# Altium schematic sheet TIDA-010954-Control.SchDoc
size 431 x 279 mm; Date: Not shown in title block; ApprovedBy: Not shown in title block; CheckedBy: Not shown in title block; Author: Not shown in title block; CompanyName: Not shown in title block; Engineer: Not shown in title block; Organization: Not shown in title block; Address1: Not shown in title block; Address2: Not shown in title block; Address3: Not shown in title block; Address4: Not shown in title block; DocumentNumber: 2; Revision: Use project parameter SCH_Rev; SheetNumber: 8; SheetTotal: 9; PageSetup: Record=PageOptions¦CenterHorizontal=True¦CenterVertical=True¦PrintScale=1.00¦XCorrection=1.00¦YCorrection=1.00¦PrintKind=0¦BorderSize=5000000¦LeftOffset=0¦BottomOffset=0¦Orientation=2¦PaperLength=1000¦PaperWidth=1000¦Scale=100¦PaperSource=15¦PrintQuality=600¦MediaType=1¦DitherType=10¦PaperKind=Letter¦PrintScaleMode=1
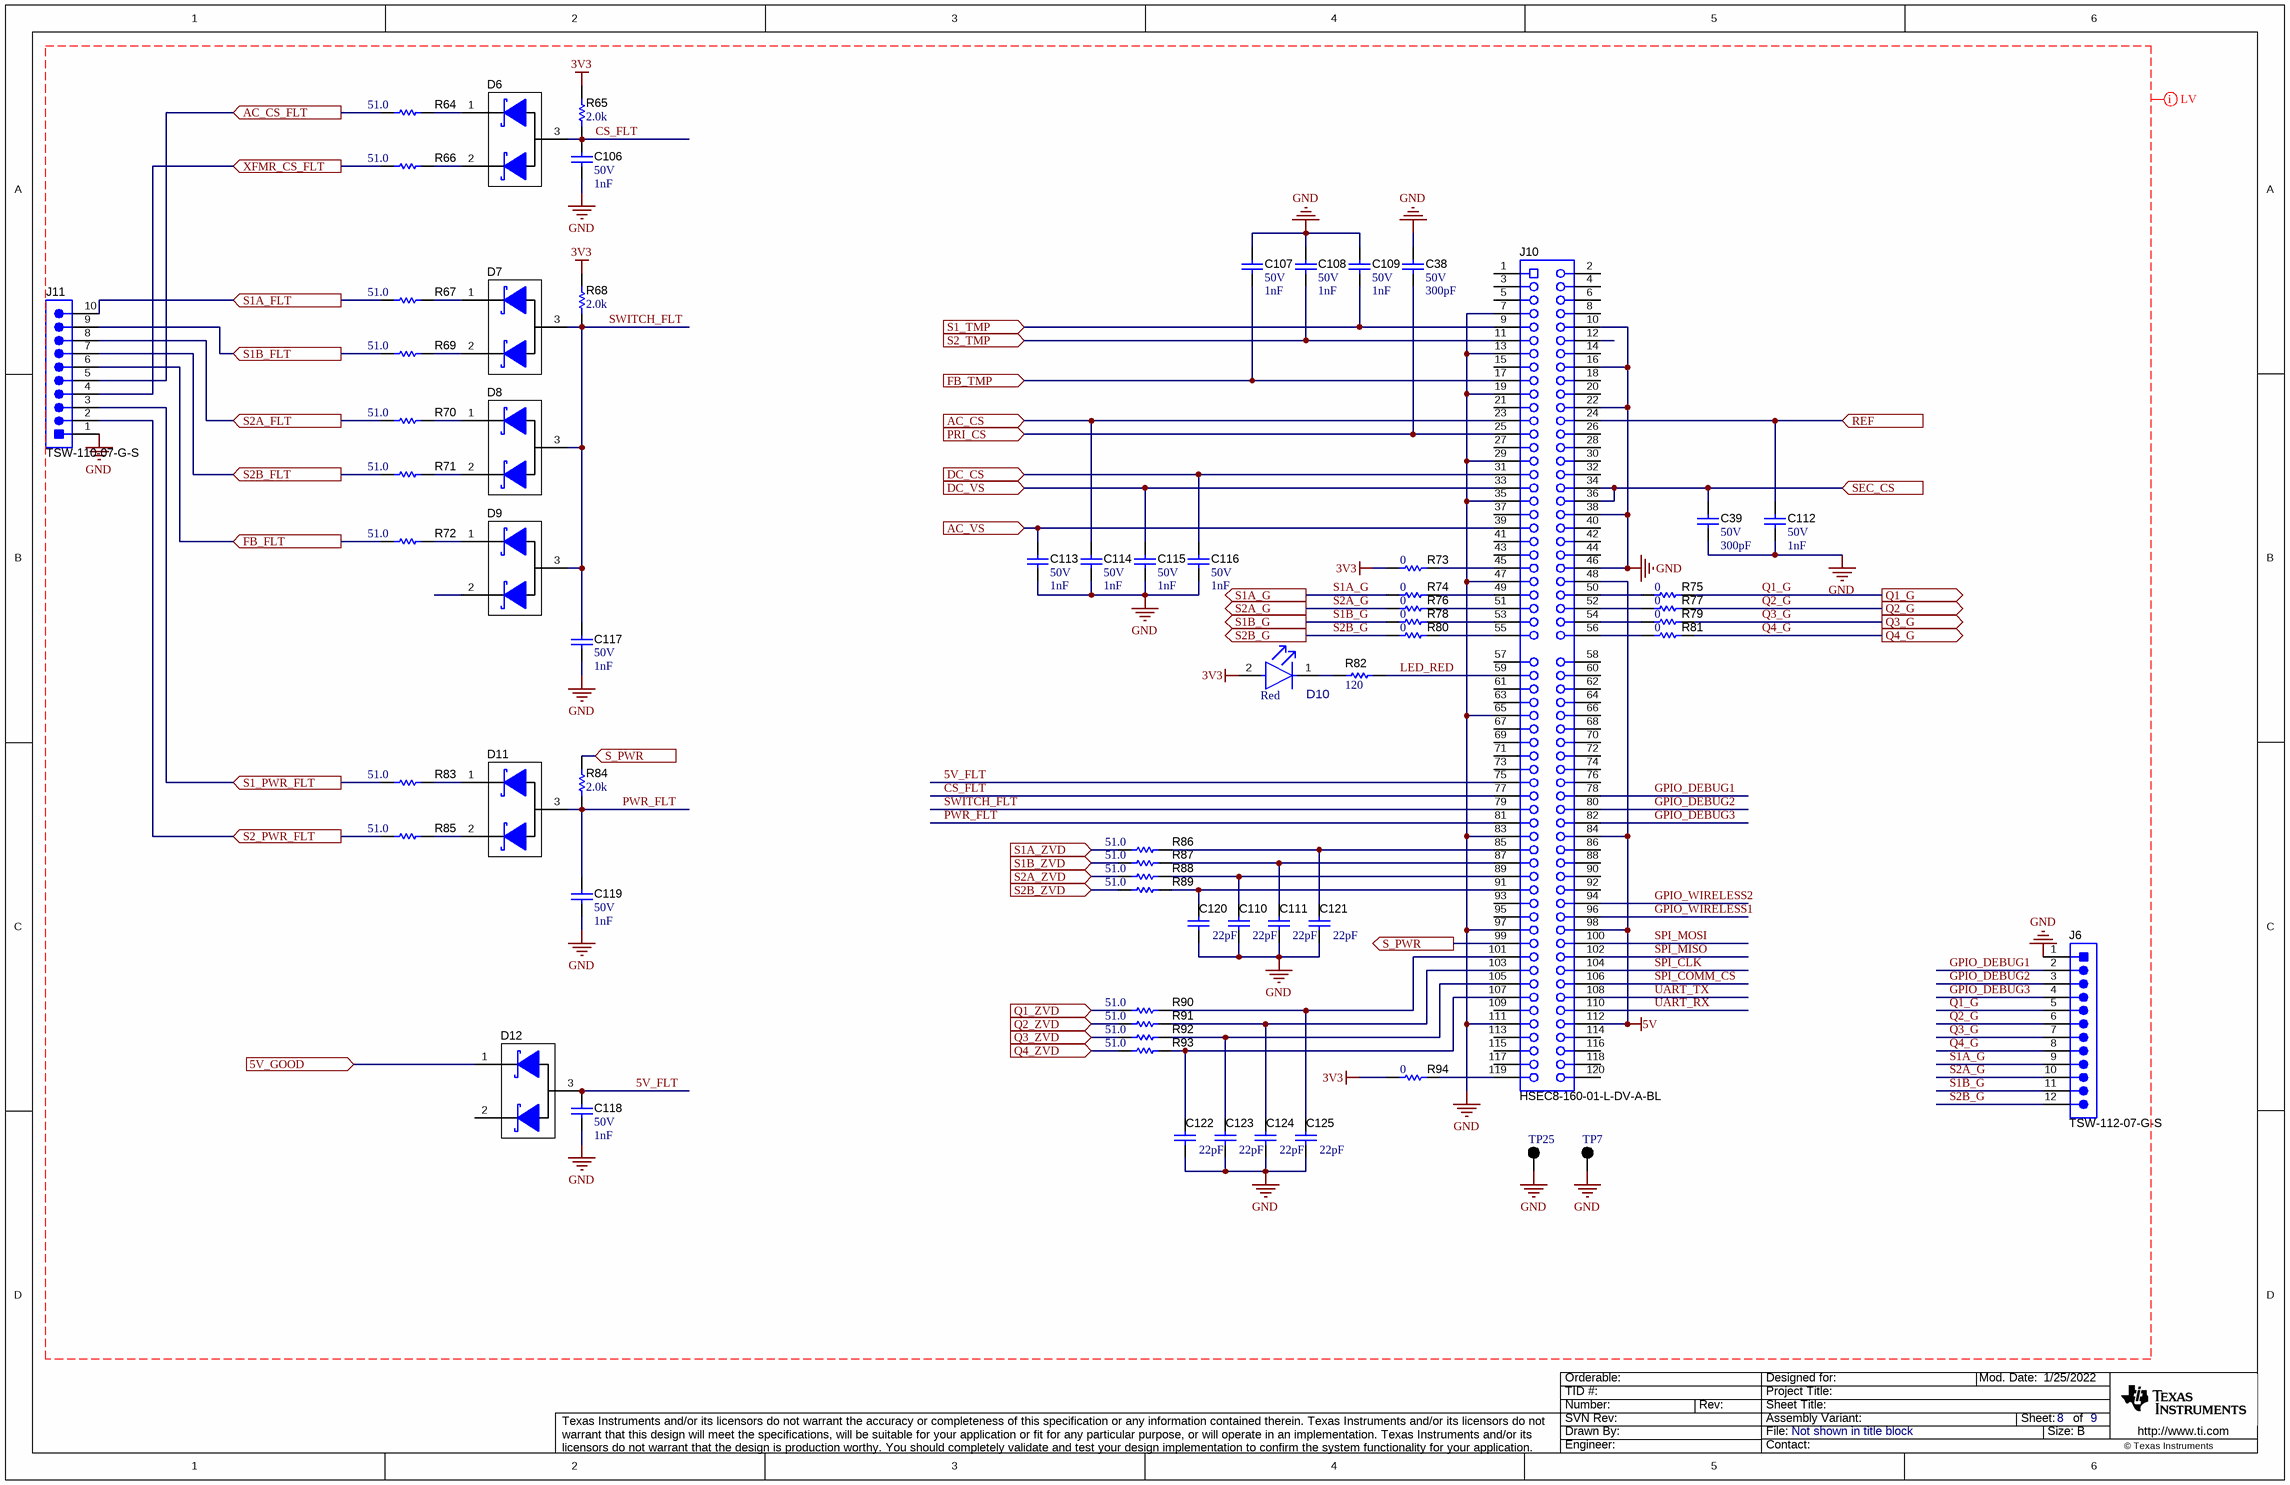
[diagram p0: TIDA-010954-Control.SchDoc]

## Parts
C38  VDC_V: 50V  ValueDisplayed: 300pF  [0603]  (hidden comment: GRM1885C1H301JA01D)
C39  VDC_V: 50V  ValueDisplayed: 300pF  [0603]  (hidden comment: GRM1885C1H301JA01D)
C106  VDC_V: 50V  ValueDisplayed: 1nF  [0603]  (hidden comment: GRM1885C1H102JA01D)
C107  VDC_V: 50V  ValueDisplayed: 1nF  [0603]  (hidden comment: GRM1885C1H102JA01D)
C108  VDC_V: 50V  ValueDisplayed: 1nF  [0603]  (hidden comment: GRM1885C1H102JA01D)
C109  VDC_V: 50V  ValueDisplayed: 1nF  [0603]  (hidden comment: GRM1885C1H102JA01D)
C110  ValueDisplayed: 22pF  [0603]  (hidden comment: GRM1885C1H220JA01D)
C111  ValueDisplayed: 22pF  [0603]  (hidden comment: GRM1885C1H220JA01D)
C112  VDC_V: 50V  ValueDisplayed: 1nF  [0603]  (hidden comment: GRM1885C1H102JA01D)
C113  VDC_V: 50V  ValueDisplayed: 1nF  [0603]  (hidden comment: GRM1885C1H102JA01D)
C114  VDC_V: 50V  ValueDisplayed: 1nF  [0603]  (hidden comment: GRM1885C1H102JA01D)
C115  VDC_V: 50V  ValueDisplayed: 1nF  [0603]  (hidden comment: GRM1885C1H102JA01D)
C116  VDC_V: 50V  ValueDisplayed: 1nF  [0603]  (hidden comment: GRM1885C1H102JA01D)
C117  VDC_V: 50V  ValueDisplayed: 1nF  [0603]  (hidden comment: GRM1885C1H102JA01D)
C118  VDC_V: 50V  ValueDisplayed: 1nF  [0603]  (hidden comment: GRM1885C1H102JA01D)
C119  VDC_V: 50V  ValueDisplayed: 1nF  [0603]  (hidden comment: GRM1885C1H102JA01D)
C120  ValueDisplayed: 22pF  [0603]  (hidden comment: GRM1885C1H220JA01D)
C121  ValueDisplayed: 22pF  [0603]  (hidden comment: GRM1885C1H220JA01D)
C122  ValueDisplayed: 22pF  [0603]  (hidden comment: GRM1885C1H220JA01D)
C123  ValueDisplayed: 22pF  [0603]  (hidden comment: GRM1885C1H220JA01D)
C124  ValueDisplayed: 22pF  [0603]  (hidden comment: GRM1885C1H220JA01D)
C125  ValueDisplayed: 22pF  [0603]  (hidden comment: GRM1885C1H220JA01D)
D6  BAT54AWT-TP  [SOT-323]  (value not drawn)
D7  BAT54AWT-TP  [SOT-323]  (value not drawn)
D8  BAT54AWT-TP  [SOT-323]  (value not drawn)
D9  BAT54AWT-TP  [SOT-323]  (value not drawn)
D10  Color: Red  [FP-APG1608SURKC_T_0603-MFG]  (hidden comment: APG1608SURKC/T)
D11  BAT54AWT-TP  [SOT-323]  (value not drawn)
D12  BAT54AWT-TP  [SOT-323]  (value not drawn)
J6  TSW-112-07-G-S  [TSW-112-07-G-S]
J10  HSEC8-160-01-L-DV-A-BL  [controlCARD-120HSEC]
J11  TSW-110-07-G-S  [TSW-110-07-G-S]
R64  ValueDisplayed: 51.0  [0603]  (hidden comment: RC0603FR-0751RL)
R65  ValueDisplayed: 2.0k  [0603]  (hidden comment: RC0603JR-072KL)
R66  ValueDisplayed: 51.0  [0603]  (hidden comment: RC0603FR-0751RL)
R67  ValueDisplayed: 51.0  [0603]  (hidden comment: RC0603FR-0751RL)
R68  ValueDisplayed: 2.0k  [0603]  (hidden comment: RC0603JR-072KL)
R69  ValueDisplayed: 51.0  [0603]  (hidden comment: RC0603FR-0751RL)
R70  ValueDisplayed: 51.0  [0603]  (hidden comment: RC0603FR-0751RL)
R71  ValueDisplayed: 51.0  [0603]  (hidden comment: RC0603FR-0751RL)
R72  ValueDisplayed: 51.0  [0603]  (hidden comment: RC0603FR-0751RL)
R73  ValueDisplayed: 0  [0603]  (hidden comment: RC0603JR-070RL)
R74  ValueDisplayed: 0  [0603]  (hidden comment: RC0603JR-070RL)
R75  ValueDisplayed: 0  [0603]  (hidden comment: RC0603JR-070RL)
R76  ValueDisplayed: 0  [0603]  (hidden comment: RC0603JR-070RL)
R77  ValueDisplayed: 0  [0603]  (hidden comment: RC0603JR-070RL)
R78  ValueDisplayed: 0  [0603]  (hidden comment: RC0603JR-070RL)
R79  ValueDisplayed: 0  [0603]  (hidden comment: RC0603JR-070RL)
R80  ValueDisplayed: 0  [0603]  (hidden comment: RC0603JR-070RL)
R81  ValueDisplayed: 0  [0603]  (hidden comment: RC0603JR-070RL)
R82  ValueDisplayed: 120  [0603]  (hidden comment: RC0603FR-07120RL)
R83  ValueDisplayed: 51.0  [0603]  (hidden comment: RC0603FR-0751RL)
R84  ValueDisplayed: 2.0k  [0603]  (hidden comment: RC0603JR-072KL)
R85  ValueDisplayed: 51.0  [0603]  (hidden comment: RC0603FR-0751RL)
R86  ValueDisplayed: 51.0  [0603]  (hidden comment: RC0603FR-0751RL)
R87  ValueDisplayed: 51.0  [0603]  (hidden comment: RC0603FR-0751RL)
R88  ValueDisplayed: 51.0  [0603]  (hidden comment: RC0603FR-0751RL)
R89  ValueDisplayed: 51.0  [0603]  (hidden comment: RC0603FR-0751RL)
R90  ValueDisplayed: 51.0  [0603]  (hidden comment: RC0603FR-0751RL)
R91  ValueDisplayed: 51.0  [0603]  (hidden comment: RC0603FR-0751RL)
R92  ValueDisplayed: 51.0  [0603]  (hidden comment: RC0603FR-0751RL)
R93  ValueDisplayed: 51.0  [0603]  (hidden comment: RC0603FR-0751RL)
R94  ValueDisplayed: 0  [0603]  (hidden comment: RC0603JR-070RL)
TP7  5011  [Keystone5011]  (value not drawn)
TP25  5011  [Keystone5011]  (value not drawn)

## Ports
5V_GOOD (in), AC_CS (in), AC_CS_FLT (in), AC_VS (in), DC_CS (in), DC_VS (in), FB_FLT (in), FB_TMP (in), PRI_CS (in), Q1_G (out), Q1_ZVD (in), Q2_G (out), Q2_ZVD (in), Q3_G (out), Q3_ZVD (in), Q4_G (out), Q4_ZVD (in), REF (in), S1_PWR_FLT (in), S1_TMP (in), S1A_FLT (in), S1A_G (out), S1A_ZVD (in), S1B_FLT (in), S1B_G (out), S1B_ZVD (in), S2_PWR_FLT (in), S2_TMP (in), S2A_FLT (in), S2A_G (out), S2A_ZVD (in), S2B_FLT (in), S2B_G (out), S2B_ZVD (in), S_PWR (in), S_PWR (out), SEC_CS (in), XFMR_CS_FLT (in)

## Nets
3V3: D10.2(ANODE) R65.2 R68.2 R73.1 R94.1
5V: J10.48 J10.84 J10.98 J10.112
GND: C38.2 C39.2 C106.2 C107.1 C108.1 C109.1 C110.2 C111.2 C112.2 C113.2 C114.2 C115.2 C116.2 C117.2 C118.2 C119.2 C120.2 C121.2 C122.2 C123.2 C124.2 C125.2 J6.1 J10.7 J10.10 J10.13 J10.16 J10.19 J10.22 J10.29 J10.35 J10.38 J10.46 J10.47 J10.65 J10.83 J10.97 J10.111 J11.1 TP7.1 TP25.1
5V_FLT: C118.1 D12.3(A) J10.75
5V_GOOD: D12.1(A) ; port 5V_GOOD
AC_CS: C114.1 J10.23 ; port AC_CS
AC_CS_FLT: J11.5 R64.1 ; port AC_CS_FLT
AC_VS: C113.1 J10.39 ; port AC_VS
CS_FLT: C106.1 D6.3(A) J10.77 R65.1
DC_CS: C116.1 J10.31 ; port DC_CS
DC_VS: C115.1 J10.33 ; port DC_VS
FB_FLT: J11.6 R72.1 ; port FB_FLT
FB_TMP: C107.2 J10.17 ; port FB_TMP
GPIO_DEBUG1: J6.2 J10.78
GPIO_DEBUG2: J6.3 J10.80
GPIO_DEBUG3: J6.4 J10.82
GPIO_WIRELESS1: J10.96
GPIO_WIRELESS2: J10.94
LED_RED: J10.59 R82.2
PRI_CS: C38.1 J10.25 ; port PRI_CS
PWR_FLT: C119.1 D11.3(A) J10.81 R84.1
Q1_G: J6.5 R75.2 ; port Q1_G
Q1_ZVD: R90.1 ; port Q1_ZVD
Q2_G: J6.6 R77.2 ; port Q2_G
Q2_ZVD: R91.1 ; port Q2_ZVD
Q3_G: J6.7 R79.2 ; port Q3_G
Q3_ZVD: R92.1 ; port Q3_ZVD
Q4_G: J6.8 R81.2 ; port Q4_G
Q4_ZVD: R93.1 ; port Q4_ZVD
REF: C112.1 J10.24 ; port REF
S1_PWR_FLT: J11.3 R83.1 ; port S1_PWR_FLT
S1_TMP: C109.2 J10.9 ; port S1_TMP
S1A_FLT: J11.10 R67.1 ; port S1A_FLT
S1A_G: J6.9 R74.1 ; port S1A_G
S1A_ZVD: R86.1 ; port S1A_ZVD
S1B_FLT: J11.9 R69.1 ; port S1B_FLT
S1B_G: J6.11 R78.1 ; port S1B_G
S1B_ZVD: R87.1 ; port S1B_ZVD
S2_PWR_FLT: J11.2 R85.1 ; port S2_PWR_FLT
S2_TMP: C108.2 J10.11 ; port S2_TMP
S2A_FLT: J11.8 R70.1 ; port S2A_FLT
S2A_G: J6.10 R76.1 ; port S2A_G
S2A_ZVD: R88.1 ; port S2A_ZVD
S2B_FLT: J11.7 R71.1 ; port S2B_FLT
S2B_G: J6.12 R80.1 ; port S2B_G
S2B_ZVD: R89.1 ; port S2B_ZVD
S_PWR: J10.99 R84.2 ; port S_PWR
SEC_CS: C39.1 J10.34 J10.36 ; port SEC_CS
SPI_CLK: J10.104
SPI_COMM_CS: J10.106
SPI_MISO: J10.102
SPI_MOSI: J10.100
SWITCH_FLT: C117.1 D7.3(A) D8.3(A) D9.3(A) J10.79 R68.1
UART_RX: J10.110
UART_TX: J10.108
XFMR_CS_FLT: J11.4 R66.1 ; port XFMR_CS_FLT
NetC110_1: C110.1 J10.89 R88.2
NetC111_1: C111.1 J10.87 R87.2
NetC120_1: C120.1 J10.91 R89.2
NetC121_1: C121.1 J10.85 R86.2
NetC122_1: C122.1 J10.107 R93.2
NetC123_1: C123.1 J10.105 R92.2
NetC124_1: C124.1 J10.103 R91.2
NetC125_1: C125.1 J10.101 R90.2
NetD6_1: D6.1(A) R64.2
NetD6_2: D6.2(K) R66.2
NetD7_1: D7.1(A) R67.2
NetD7_2: D7.2(K) R69.2
NetD8_1: D8.1(A) R70.2
NetD8_2: D8.2(K) R71.2
NetD9_1: D9.1(A) R72.2
NetD10_1: D10.1(CATHODE) R82.1
NetD11_1: D11.1(A) R83.2
NetD11_2: D11.2(K) R85.2
NetJ10_45: J10.45 R73.2
NetJ10_49: J10.49 R74.2
NetJ10_50: J10.50 R75.1
NetJ10_51: J10.51 R76.2
NetJ10_52: J10.52 R77.1
NetJ10_53: J10.53 R78.2
NetJ10_54: J10.54 R79.1
NetJ10_55: J10.55 R80.2
NetJ10_56: J10.56 R81.1
NetJ10_119: J10.119 R94.2

Not connected (* = marked no-connect by the designer): D9 2(K); D12 2(K); J10 1 2 3 4 5 6 8 12 14 15 18 20 21 26 27 28 30 32 37 40 41 42 43 44 57 58 60 61 62 63 64 66 67 68 69 70 71 72 73 74 76 86 88 90 92 93 95 109 113 114 115 116 117 118 120

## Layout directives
net class LV: 3V3, 5V, 5V_FLT, CS_FLT, GND, GPIO_DEBUG1, GPIO_DEBUG2, GPIO_DEBUG3, GPIO_WIRELESS1, GPIO_WIRELESS2, LED_RED, PWR_FLT, Q1_G, Q2_G, Q3_G, Q4_G, S1A_G, S1B_G, S2A_G, S2B_G, SPI_CLK, SPI_COMM_CS, SPI_MISO, SPI_MOSI, SWITCH_FLT, UART_RX, UART_TX

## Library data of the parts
C38 C39 = CMP-0007206-4: CAP, CERM, 300 pF, 50 V, +/- 5%, C0G/NP0, 0603; Manufacturer: MuRata; TaMin_C: -55°C; Polarized: N; SizeAreaWB_mm2: 4.68; Value1: Unknown; U/M: EA; Value: 300pF; TaMax_C: 125°C; SizeZ_mm: 1; SizeX_mm: 1.6; SizeY_mm: 0.8; SizeArea_mm2: 1.28; AEC Category: Q200
C106-C109 C112-C119 = CMP-0007173-4: CAP, CERM, 1000 pF, 50 V, +/- 5%, C0G/NP0, 0603; Manufacturer: MuRata; TaMin_C: -55°C; Polarized: N; SizeAreaWB_mm2: 4.68; Value1: Unknown; U/M: EA; Value: 1000pF; TaMax_C: 125°C; SizeZ_mm: 1; SizeX_mm: 1.6; SizeY_mm: 0.8; SizeArea_mm2: 1.28; AEC Category: Q200
C110 C111 C120-C125 = CMP-0007196-4: CAP, CERM, 22 pF, 50 V, +/- 5%, C0G/NP0, 0603; Manufacturer: MuRata; TaMin_C: -55°C; Polarized: N; SizeAreaWB_mm2: 4.68; Value1: Unknown; U/M: EA; Value: 22pF; TaMax_C: 125°C; SizeZ_mm: 1; SizeX_mm: 1.6; SizeY_mm: 0.8; Value2: 50V; SizeArea_mm2: 1.28; AEC Category: Q200
D6-D9 D11 D12 = CMP-0028627-2: Diode, Schottky, 30 V, 0.2 A, SOT-323; Manufacturer: Micro Commercial Components; SizeArea_mm2: 4.84; Io_A: 200mA; Value2: 1V; Value1: 0.2A; TJmax_C: 125°C; SizeY_mm: 2.2; AEC Category: Q101; SizeZ_mm: 1.1; Green_REACh: Incomplete; Value: 30V; Green_Lifecycle: Not Set; SizeAreaWB_mm2: 10.24
D10 = CMP-0091305-2: Red 630nm LED Indication - Discrete 2V 0603 (1608 Metric); Manufacturer: Kingbright; AEC Qualified: No; Import Ts: 1521847491; Forward Current: 20mA; Vr_V: 5V; Ciiva Ids: 1546259; Luminous Intensity: 110mcd; Power_TotalModule: 75mW; Tjmax_C: 115°C; Led Orientation: Top View; SizeZ_mm: 0.28mm; LambdaP: 645nm; Angle: 120°
J6 = CMP-0075424-1: Header, 100mil, 12x1, Gold, TH; Manufacturer: Samtec; Pitch_mm: 2.54; Cert_VDE: N; Gender: Male; Cert_CSA: Y; Current_A: 6.3A; Voltage_V: 550V; CT: False; Row_Count: 1; CNHeader: True
J10 = CMP-0003814-2: C2000 controlCARD-120HSEC connector, SMT; Manufacturer: Samtec; Note: The pin numbering does not match Samtec datasheet
J11 = CMP-0075422-1: Header, 100mil, 10x1, Gold, TH; Manufacturer: Samtec; Pitch_mm: 2.54; Cert_VDE: N; Gender: Male; Cert_CSA: Y; Voltage_V: 550V; Green_REACh: Passed; Current_A: 6.3A; CT: False; Green_Lifecycle: Active; Row_Count: 1; CNHeader: True
R64 R66 R67 R69-R72 R83 R85-R93 = CMP-0023169-5: RES, 51.0, 1%, 0.1 W, 0603; Manufacturer: Yageo; Power_W: 100mW; TempCo: 100 ppm/C; Value_Code: 51R0; Value: 51.0; Res_ohm: 51; SizeX_mm: 1.6; SizeY_mm: 0.8; SizeZ_mm: 1; Value2: 0.1W; SizeArea_mm2: 1.28; AEC Qualified: N; VDC_V: 75V; AEC Category: Q200; SizeAreaWB_mm2: 4.68
R65 R68 R84 = CMP-0025909-5: RES, 2.0 k, 5%, 0.1 W, 0603; Manufacturer: Yageo; Power_W: 100mW; TempCo: 100 ppm/C; Value_Code: 2k00; Value: 2.0k; EIA_Code: E24; Res_ohm: 2k; SizeX_mm: 1.6; SizeY_mm: 0.8; SizeZ_mm: 1; Value2: 0.1W; SizeArea_mm2: 1.28; AEC Qualified: N; VDC_V: 75V; AEC Category: Q200; SizeAreaWB_mm2: 4.68
R73-R81 R94 = CMP-0025885-5: RES, 0, 5%, 0.1 W, 0603; Manufacturer: Yageo; Power_W: 100mW; TempCo: 200 ppm/C; Value_Code: 0000; Value: 0; EIA_Code: E24; SizeX_mm: 1.6; SizeZ_mm: 1; Value2: 0.1W; SizeArea_mm2: 1.28; AEC Qualified: N; VDC_V: 75V; AEC Category: Q200; SizeY_mm: 0.8; SizeAreaWB_mm2: 4.68
R82 = CMP-0022769-5: RES, 120, 1%, 0.1 W, 0603; Manufacturer: Yageo; Power_W: 100mW; TempCo: 100 ppm/C; Value_Code: 120R; Value: 120; SizeX_mm: 1.6; SizeY_mm: 0.8; SizeZ_mm: 1; Value2: 0.1W; SizeArea_mm2: 1.28; AEC Qualified: N; VDC_V: 75V; AEC Category: Q200; SizeAreaWB_mm2: 4.68
TP7 TP25 = CMP-0055148-2: Test Point, Multipurpose, Black, TH; Manufacturer: Keystone Electronics; CNHeader: FALSE; ContactFinish: Silver; Green_REACh: Passed; Green_Lifecycle: Active; CT: TRUE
